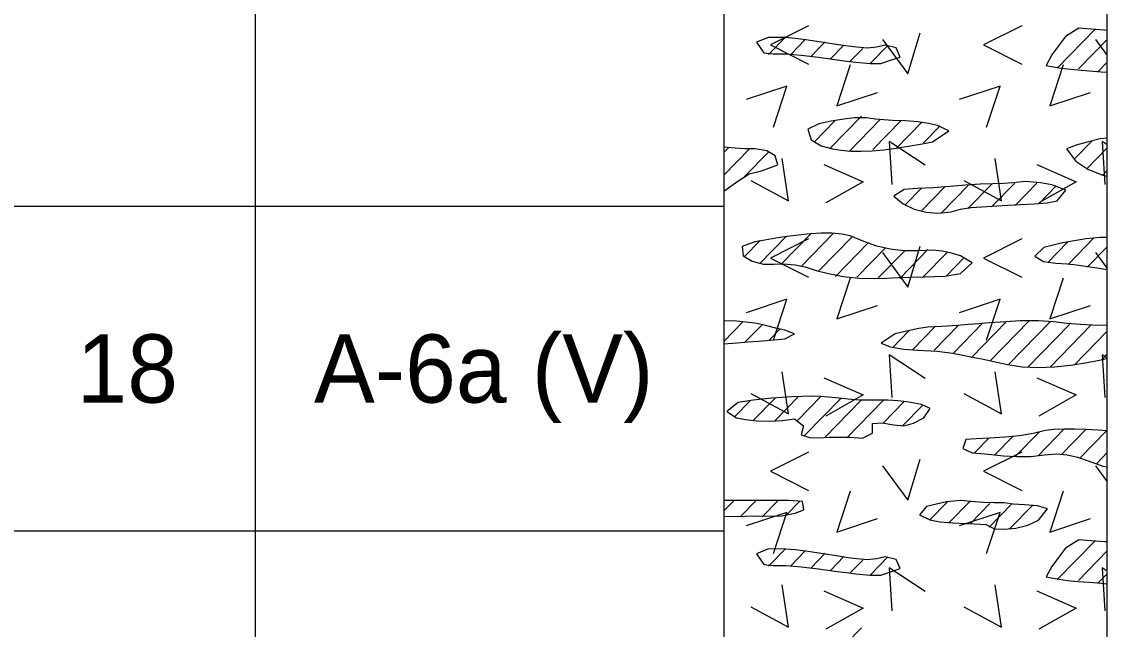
# Model space of a CAD drawing. Extents: x 0 to 0.833, y -0.323 to 0.608.
# Drawn here: x 0.7272 to 0.8333, y 0.1491 to 0.2085 of the extents above; entities that cross this region are included whole.
import ezdxf

# ---------------------------------------------------------------- set-up
doc = ezdxf.new("R2010")
doc.units = 0

msp = doc.modelspace()

# ---------------------------------------------------------------- linework, layer by layer
for points in [[(0, -0.32328), (0.83333, -0.32328), (0.83333, 0.60833), (0, 0.60833)], [(0.83305, 0.20768), (0.83171, 0.20779), (0.83054, 0.20789), (0.82925, 0.20707), (0.82857, 0.20616), (0.82792, 0.20527), (0.82735, 0.20425), (0.82858, 0.20402), (0.82945, 0.20392), (0.83045, 0.20382), (0.83155, 0.20373), (0.83272, 0.20363), (0.83333, 0.20358), (0.83333, 0.20767)], [(0.80066, 0.20538), (0.80188, 0.20537), (0.80339, 0.20524), (0.80423, 0.20515), (0.8051, 0.20504), (0.806, 0.20492), (0.80692, 0.2048), (0.80784, 0.20468), (0.80875, 0.20457), (0.81014, 0.20443), (0.81119, 0.20444), (0.81222, 0.20478), (0.81308, 0.20507), (0.81267, 0.20597), (0.8116, 0.20622), (0.81075, 0.20602), (0.80989, 0.20594), (0.80885, 0.20602), (0.80799, 0.20613), (0.80703, 0.20627), (0.806, 0.20644), (0.80492, 0.2066), (0.80384, 0.20676), (0.8028, 0.20689), (0.80182, 0.20698), (0.8002, 0.20699), (0.79901, 0.20652), (0.79974, 0.20548)], [(0.81233, 0.19887), (0.81063, 0.19899), (0.80977, 0.19912), (0.8086, 0.19913), (0.80755, 0.19899), (0.80632, 0.19879), (0.80513, 0.19854), (0.80403, 0.19802), (0.80436, 0.19696), (0.80536, 0.1964), (0.80647, 0.1961), (0.8073, 0.19595), (0.80824, 0.19587), (0.80926, 0.19586), (0.81035, 0.19591), (0.81149, 0.19601), (0.81267, 0.19616), (0.81386, 0.19635), (0.81506, 0.19656), (0.81625, 0.19679), (0.81783, 0.19787), (0.81673, 0.19837), (0.81585, 0.19858), (0.8148, 0.19873), (0.81361, 0.19883)], [(0.83265, 0.19706), (0.83136, 0.19675), (0.83028, 0.19647), (0.82934, 0.19608), (0.83026, 0.19488), (0.83142, 0.19412), (0.83279, 0.19354), (0.83333, 0.19344), (0.83333, 0.19715)], [(0.79583, 0.19196), (0.79719, 0.19295), (0.79831, 0.19365), (0.79951, 0.19393), (0.80111, 0.19453), (0.80086, 0.19541), (0.80002, 0.19589), (0.79889, 0.19608), (0.79791, 0.19611), (0.79694, 0.19617), (0.79583, 0.19625)], [(0.82537, 0.19291), (0.82408, 0.19276), (0.82319, 0.1927), (0.82214, 0.19267), (0.82091, 0.19264), (0.81947, 0.19255), (0.81792, 0.19243), (0.81632, 0.1923), (0.81475, 0.19221), (0.81348, 0.19211), (0.81247, 0.19147), (0.81337, 0.19071), (0.81444, 0.19021), (0.81561, 0.18992), (0.81675, 0.18981), (0.81807, 0.18993), (0.81896, 0.1902), (0.82003, 0.19035), (0.82157, 0.19047), (0.82253, 0.19053), (0.82362, 0.19058), (0.82483, 0.19065), (0.82618, 0.19071), (0.82745, 0.19082), (0.82842, 0.191), (0.82927, 0.19205), (0.82791, 0.19257), (0.82679, 0.19277)], [(0.79885, 0.187), (0.79763, 0.18654), (0.79773, 0.18564), (0.79859, 0.18512), (0.7997, 0.18482), (0.80074, 0.18483), (0.80165, 0.18484), (0.80281, 0.18476), (0.80377, 0.18455), (0.80486, 0.1842), (0.80606, 0.18391), (0.80751, 0.18363), (0.80905, 0.18345), (0.81052, 0.18342), (0.81177, 0.18347), (0.81289, 0.18352), (0.81408, 0.18355), (0.81553, 0.18359), (0.81642, 0.18362), (0.81745, 0.18365), (0.81897, 0.18392), (0.82011, 0.18496), (0.81896, 0.18563), (0.8181, 0.18589), (0.81717, 0.18609), (0.81626, 0.1862), (0.81479, 0.18614), (0.81343, 0.18614), (0.8121, 0.18629), (0.8108, 0.18659), (0.80953, 0.18705), (0.8082, 0.1876), (0.80736, 0.18776), (0.8064, 0.18784), (0.80536, 0.18784), (0.80427, 0.18778), (0.80314, 0.18767), (0.80201, 0.18752), (0.8009, 0.18735), (0.79984, 0.18717)], [(0.83263, 0.18744), (0.83126, 0.18731), (0.82969, 0.18704), (0.82883, 0.18687), (0.82712, 0.18646), (0.82623, 0.18559), (0.82708, 0.1851), (0.82831, 0.18491), (0.82941, 0.18484), (0.83033, 0.18475), (0.83165, 0.18457), (0.83253, 0.18443), (0.83333, 0.18429), (0.83333, 0.18744)], [(0.79583, 0.17704), (0.79715, 0.17715), (0.79814, 0.17722), (0.79922, 0.1773), (0.80039, 0.17739), (0.80179, 0.17751), (0.80275, 0.17802), (0.80179, 0.17836), (0.80091, 0.17858), (0.80003, 0.1788), (0.79909, 0.17901), (0.79803, 0.17917), (0.79677, 0.17927), (0.79583, 0.17925)], [(0.82816, 0.17479), (0.82978, 0.17496), (0.83137, 0.17521), (0.8329, 0.17552), (0.83333, 0.17563), (0.83333, 0.17887), (0.83295, 0.17884), (0.83188, 0.17886), (0.83071, 0.17891), (0.82938, 0.17901), (0.82807, 0.17918), (0.82662, 0.1793), (0.82576, 0.1793), (0.82484, 0.17928), (0.82387, 0.17923), (0.82286, 0.17916), (0.82182, 0.17908), (0.82077, 0.17899), (0.81973, 0.17891), (0.81872, 0.17884), (0.81715, 0.17874), (0.81579, 0.17865), (0.81491, 0.17852), (0.81357, 0.17824), (0.8126, 0.17803), (0.81121, 0.17711), (0.8121, 0.17675), (0.81345, 0.1765), (0.81479, 0.17641), (0.81668, 0.17631), (0.81818, 0.17611), (0.81905, 0.17596), (0.82, 0.17578), (0.82107, 0.17557), (0.82225, 0.17532), (0.82357, 0.17503), (0.82501, 0.1748), (0.82656, 0.17473)], [(0.79708, 0.16981), (0.79794, 0.16963), (0.79904, 0.16952), (0.80028, 0.16949), (0.80156, 0.16954), (0.80274, 0.1697), (0.80361, 0.16903), (0.80338, 0.16814), (0.80422, 0.16787), (0.80517, 0.16785), (0.80613, 0.1679), (0.8072, 0.16793), (0.80818, 0.1679), (0.80939, 0.16783), (0.81037, 0.1683), (0.81038, 0.16924), (0.8113, 0.16931), (0.81244, 0.16912), (0.81346, 0.16901), (0.81438, 0.16927), (0.81539, 0.16981), (0.81601, 0.17072), (0.81517, 0.1711), (0.81374, 0.17137), (0.81285, 0.17146), (0.81187, 0.17152), (0.81, 0.17152), (0.8091, 0.17154), (0.808, 0.17162), (0.80678, 0.17177), (0.8053, 0.1719), (0.80443, 0.17192), (0.80349, 0.1719), (0.80251, 0.17186), (0.80152, 0.1718), (0.80054, 0.17172), (0.79959, 0.17163), (0.7987, 0.17153), (0.79722, 0.17131), (0.79614, 0.17043)], [(0.83241, 0.16859), (0.83129, 0.16866), (0.83017, 0.16869), (0.8291, 0.1687), (0.82811, 0.16866), (0.82728, 0.16857), (0.82608, 0.16827), (0.82476, 0.16804), (0.8233, 0.16791), (0.82183, 0.16782), (0.82051, 0.16776), (0.81951, 0.16767), (0.81922, 0.1668), (0.82013, 0.16638), (0.82097, 0.16633), (0.822, 0.16623), (0.82318, 0.1661), (0.82448, 0.16601), (0.82584, 0.16604), (0.82719, 0.1662), (0.82836, 0.16627), (0.8294, 0.16619), (0.83043, 0.16595), (0.83156, 0.16556), (0.83291, 0.16507), (0.83333, 0.165), (0.83333, 0.16852)], [(0.79583, 0.16018), (0.79676, 0.16017), (0.79792, 0.16019), (0.79882, 0.16023), (0.79992, 0.16018), (0.80151, 0.16023), (0.80282, 0.16048), (0.80367, 0.1608), (0.80354, 0.16164), (0.80216, 0.16173), (0.79583, 0.16173)], [(0.81822, 0.15953), (0.81944, 0.15948), (0.82033, 0.15943), (0.82145, 0.15937), (0.82229, 0.15895), (0.82324, 0.15891), (0.82438, 0.15901), (0.82555, 0.1593), (0.82662, 0.15981), (0.82749, 0.1609), (0.82651, 0.16121), (0.82524, 0.16131), (0.82413, 0.16137), (0.82324, 0.16148), (0.82226, 0.1615), (0.82121, 0.16152), (0.81995, 0.16161), (0.81902, 0.16173), (0.81761, 0.16159), (0.81566, 0.16114), (0.81496, 0.16031), (0.81598, 0.15982), (0.81695, 0.15964)], [(0.83305, 0.15768), (0.83171, 0.15779), (0.83054, 0.15789), (0.82925, 0.15707), (0.82857, 0.15616), (0.82792, 0.15527), (0.82735, 0.15425), (0.82858, 0.15402), (0.82945, 0.15392), (0.83045, 0.15382), (0.83155, 0.15373), (0.83272, 0.15363), (0.83333, 0.15358), (0.83333, 0.15767)], [(0.80066, 0.15538), (0.80188, 0.15537), (0.80339, 0.15524), (0.80423, 0.15515), (0.8051, 0.15504), (0.806, 0.15492), (0.80692, 0.1548), (0.80784, 0.15468), (0.80875, 0.15457), (0.81014, 0.15443), (0.81119, 0.15444), (0.81222, 0.15478), (0.81308, 0.15507), (0.81267, 0.15597), (0.8116, 0.15622), (0.81075, 0.15602), (0.80989, 0.15594), (0.80885, 0.15602), (0.80799, 0.15613), (0.80703, 0.15627), (0.806, 0.15644), (0.80492, 0.1566), (0.80384, 0.15676), (0.8028, 0.15689), (0.80182, 0.15698), (0.8002, 0.15699), (0.79901, 0.15652), (0.79974, 0.15548)]]:
    msp.add_lwpolyline(points, close=True)
for points in [[(0.75, 0.55417), (0.75, -0.28575)], [(0.75, 0.55417), (0.75, -0.28575)], [(0.79583, 0.55417), (0.79583, -0.28575)], [(0.83333, -0.28575), (0.83333, 0.50165)], [(0.80412, 0.20813), (0.80038, 0.20626), (0.80412, 0.20438)], [(0.82496, 0.20813), (0.82121, 0.20626), (0.82496, 0.20438)], [(0.80188, 0.20703), (0.8002, 0.20531)], [(0.81134, 0.20679), (0.81384, 0.20342), (0.81503, 0.20742)], [(0.83217, 0.20781), (0.82844, 0.20399)], [(0.8038, 0.20679), (0.80237, 0.20533)], [(0.80575, 0.20657), (0.80429, 0.20508)], [(0.80758, 0.20624), (0.80627, 0.20489)], [(0.81188, 0.20621), (0.81016, 0.20446)], [(0.83333, 0.20679), (0.83052, 0.20391)], [(0.83217, 0.20679), (0.83333, 0.20523)], [(0.80941, 0.2059), (0.80816, 0.20462)], [(0.80818, 0.2043), (0.80687, 0.2003), (0.81087, 0.20161)], [(0.82901, 0.2043), (0.8277, 0.2003), (0.8317, 0.20161)], [(0.83333, 0.20457), (0.83245, 0.20367)], [(0.80069, 0.19822), (0.802, 0.20222), (0.798, 0.20091)], [(0.82152, 0.19822), (0.82284, 0.20222), (0.81884, 0.20091)], [(0.80465, 0.19675), (0.80667, 0.19883)], [(0.80626, 0.19619), (0.80928, 0.19928)], [(0.80809, 0.19585), (0.81111, 0.19895)], [(0.81041, 0.19602), (0.81318, 0.19885)], [(0.81264, 0.19609), (0.81518, 0.19869)], [(0.81536, 0.19667), (0.81699, 0.19833)], [(0.81551, 0.19449), (0.81201, 0.19681), (0.81226, 0.19262)], [(0.8301, 0.19509), (0.83184, 0.19688)], [(0.83333, 0.19648), (0.83284, 0.19681), (0.83309, 0.19262)], [(0.7963, 0.19621), (0.79583, 0.19573)], [(0.79834, 0.19608), (0.79583, 0.19351)], [(0.79786, 0.19338), (0.80023, 0.19581)], [(0.83131, 0.19412), (0.83333, 0.19619)], [(0.79847, 0.19301), (0.80215, 0.19101), (0.80153, 0.19514)], [(0.80562, 0.19456), (0.80946, 0.19287), (0.80581, 0.19081)], [(0.8193, 0.19301), (0.82299, 0.19101), (0.82236, 0.19514)], [(0.82645, 0.19456), (0.83029, 0.19287), (0.82664, 0.19081)], [(0.83285, 0.19349), (0.83333, 0.19398)], [(0.81519, 0.19228), (0.81354, 0.19058)], [(0.81514, 0.19001), (0.81748, 0.19241)], [(0.81709, 0.1898), (0.81974, 0.19251)], [(0.8197, 0.19025), (0.82203, 0.19265)], [(0.82202, 0.19042), (0.8243, 0.19275)], [(0.82431, 0.19055), (0.82644, 0.19274)], [(0.82663, 0.19071), (0.82834, 0.19247)], [(0.725, 0.1905), (0.75, 0.1905)], [(0.75, 0.1905), (0.79583, 0.1905)], [(0.79938, 0.18713), (0.79786, 0.18558)], [(0.79933, 0.18487), (0.80195, 0.18756)], [(0.80412, 0.1873), (0.80038, 0.18542), (0.80412, 0.18355)], [(0.80142, 0.1848), (0.8043, 0.18775)], [(0.80653, 0.18783), (0.8034, 0.18461)], [(0.80506, 0.1841), (0.8084, 0.18753)], [(0.80997, 0.18693), (0.80675, 0.18362)], [(0.82496, 0.1873), (0.82121, 0.18542), (0.82496, 0.18355)], [(0.82751, 0.18498), (0.82945, 0.18696)], [(0.83203, 0.18739), (0.82949, 0.18479)], [(0.81164, 0.18642), (0.80884, 0.18356)], [(0.81353, 0.18614), (0.81094, 0.18349)], [(0.81134, 0.18596), (0.81384, 0.18258), (0.81503, 0.18658)], [(0.81303, 0.18342), (0.81579, 0.18625)], [(0.81534, 0.18358), (0.81768, 0.18597)], [(0.83138, 0.18452), (0.83333, 0.18652)], [(0.83217, 0.18596), (0.83333, 0.1844)], [(0.8176, 0.18368), (0.81934, 0.18547)], [(0.83333, 0.1843), (0.83333, 0.18431)], [(0.80818, 0.18347), (0.80687, 0.17947), (0.81087, 0.18078)], [(0.82901, 0.18347), (0.8277, 0.17947), (0.8317, 0.18078)], [(0.80069, 0.17739), (0.802, 0.18139), (0.798, 0.18007)], [(0.82152, 0.17739), (0.82284, 0.18139), (0.81884, 0.18007)], [(0.79765, 0.17915), (0.79583, 0.17728)], [(0.7996, 0.17894), (0.79786, 0.17716)], [(0.8013, 0.17846), (0.80027, 0.17741)], [(0.8143, 0.17648), (0.8165, 0.17873)], [(0.8164, 0.17641), (0.81879, 0.17886)], [(0.81829, 0.17613), (0.82114, 0.17905)], [(0.82004, 0.17571), (0.82346, 0.17922)], [(0.82569, 0.17929), (0.82184, 0.17535)], [(0.82775, 0.17919), (0.8237, 0.17505)], [(0.82964, 0.17892), (0.82557, 0.17474)], [(0.83173, 0.17885), (0.82774, 0.17476)], [(0.81392, 0.1783), (0.81235, 0.17669)], [(0.83333, 0.17827), (0.83012, 0.17498)], [(0.81551, 0.17366), (0.81201, 0.17597), (0.81226, 0.17178)], [(0.83281, 0.17552), (0.83333, 0.17606)], [(0.83333, 0.17565), (0.83284, 0.17597), (0.83309, 0.17178)], [(0.79847, 0.17218), (0.80215, 0.17018), (0.80153, 0.1743)], [(0.8193, 0.17218), (0.82299, 0.17018), (0.82236, 0.1743)], [(0.80562, 0.17372), (0.80946, 0.17204), (0.80581, 0.16998)], [(0.82645, 0.17372), (0.83029, 0.17204), (0.82664, 0.16998)], [(0.79844, 0.17149), (0.79691, 0.16992)], [(0.79871, 0.16955), (0.80085, 0.17174)], [(0.80083, 0.16951), (0.80311, 0.17185)], [(0.80534, 0.17192), (0.80299, 0.16951)], [(0.80367, 0.168), (0.80732, 0.17174)], [(0.80571, 0.16788), (0.80924, 0.17149)], [(0.81142, 0.17151), (0.80785, 0.16786)], [(0.81141, 0.16929), (0.81348, 0.17141)], [(0.81528, 0.17105), (0.81331, 0.16903)], [(0.82035, 0.16637), (0.82176, 0.16782)], [(0.82233, 0.16619), (0.82408, 0.16798)], [(0.82433, 0.16602), (0.82666, 0.16841)], [(0.82909, 0.1687), (0.82656, 0.1661)], [(0.82885, 0.16623), (0.83122, 0.16866)], [(0.83325, 0.16852), (0.83065, 0.16586)], [(0.80412, 0.16646), (0.80038, 0.16459), (0.80412, 0.16271)], [(0.81134, 0.16512), (0.81384, 0.16175), (0.81503, 0.16575)], [(0.82496, 0.16646), (0.82121, 0.16459), (0.82496, 0.16271)], [(0.83333, 0.1664), (0.83227, 0.16531)], [(0.83217, 0.16512), (0.83333, 0.16356)], [(0.80818, 0.16263), (0.80687, 0.15863), (0.81087, 0.15995)], [(0.82901, 0.16263), (0.8277, 0.15863), (0.8317, 0.15995)], [(0.79583, 0.1607), (0.79681, 0.1617)], [(0.79898, 0.16172), (0.79747, 0.16017)], [(0.80116, 0.16173), (0.79959, 0.16013)], [(0.80328, 0.16169), (0.80188, 0.16026)], [(0.8177, 0.16159), (0.81596, 0.15981)], [(0.81988, 0.16161), (0.81785, 0.15953)], [(0.82185, 0.16142), (0.81997, 0.15949)], [(0.824, 0.16141), (0.82178, 0.15913)], [(0.80069, 0.15655), (0.802, 0.16055), (0.798, 0.15924)], [(0.82152, 0.15655), (0.82284, 0.16055), (0.81884, 0.15924)], [(0.82601, 0.16125), (0.82378, 0.15897)], [(0.725, 0.15875), (0.75, 0.15875)], [(0.75, 0.15875), (0.79583, 0.15875)], [(0.83217, 0.15781), (0.82844, 0.15399)], [(0.80188, 0.15703), (0.8002, 0.15531)], [(0.8038, 0.15679), (0.80237, 0.15533)], [(0.80575, 0.15657), (0.80429, 0.15508)], [(0.80758, 0.15624), (0.80627, 0.15489)], [(0.81188, 0.15621), (0.81016, 0.15446)], [(0.83333, 0.15679), (0.83052, 0.15391)], [(0.80941, 0.1559), (0.80816, 0.15462)], [(0.81551, 0.15283), (0.81201, 0.15514), (0.81226, 0.15095)], [(0.83333, 0.15482), (0.83284, 0.15514), (0.83309, 0.15095)], [(0.83333, 0.15457), (0.83245, 0.15367)], [(0.79847, 0.15134), (0.80215, 0.14934), (0.80153, 0.15347)], [(0.80562, 0.15289), (0.80946, 0.15121), (0.80581, 0.14914)], [(0.8193, 0.15134), (0.82299, 0.14934), (0.82236, 0.15347)], [(0.82645, 0.15289), (0.83029, 0.15121), (0.82664, 0.14914)], [(0.80626, 0.14619), (0.80928, 0.14928)]]:
    msp.add_lwpolyline(points)

# ---------------------------------------------------------------- texts
for s, p in [('18', (0.73253, 0.17129)), ('A-6a (V)', (0.75575, 0.17129))]:
    msp.add_text(s, height=0.006667).set_placement(p)

doc.saveas('drawing.dxf')
